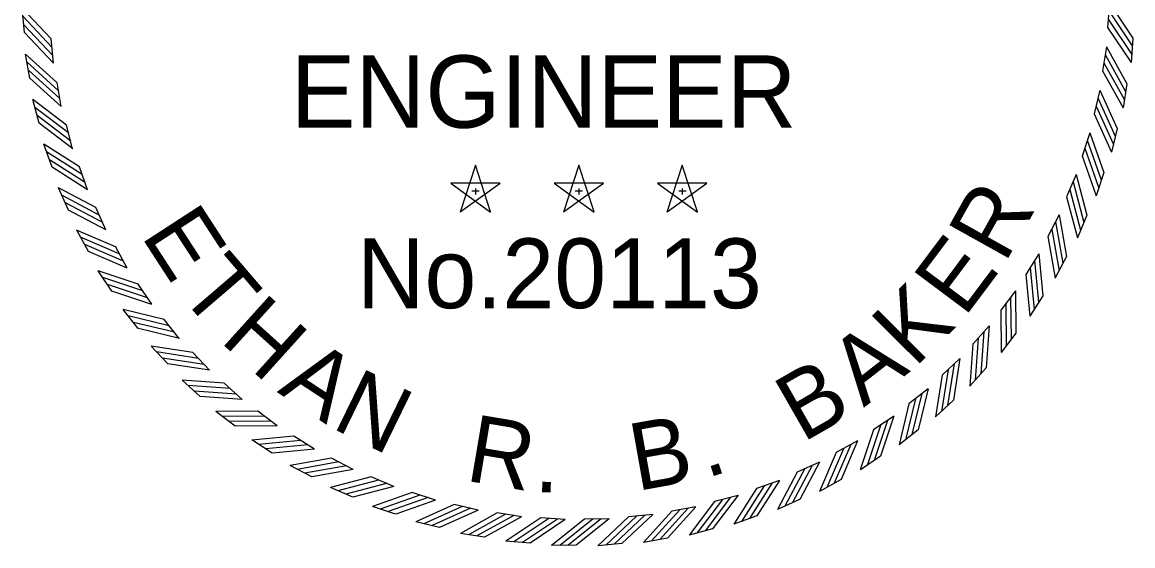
# Model space of a CAD drawing. Extents: x 18 to 14744716, y -5 to 1829144.
# Drawn here: x 42.058 to 44.119, y -4.046 to -3.074 of the extents above; entities that cross this region are included whole.
import ezdxf

# ---------------------------------------------------------------- set-up
doc = ezdxf.new("R2010")
doc.units = 0
doc.layers.add('B_StampERBB', color=7, linetype='Continuous')

msp = doc.modelspace()

# ---------------------------------------------------------------- linework, layer by layer
at = {"layer": 'B_StampERBB'}
for p, q in [((42.0623, -3.0928), (42.0581, -3.0478)), ((44.0753, -3.0382), (44.072, -3.0834)), ((42.1159, -3.1499), (42.1117, -3.1047)), ((44.1188, -3.1033), (44.1155, -3.1484)), ((44.0699, -3.1194), (44.0628, -3.1642)), ((42.0724, -3.1775), (42.0645, -3.1329)), ((42.1305, -3.2299), (42.1227, -3.1853)), ((44.1078, -3.1879), (44.1008, -3.2326)), ((44.0577, -3.1999), (44.047, -3.2439)), ((42.0895, -3.261), (42.078, -3.2173)), ((42.1517, -3.3085), (42.1402, -3.2646)), ((44.0899, -3.2712), (44.0792, -3.3152)), ((44.039, -3.2791), (44.0247, -3.3221)), ((42.1134, -3.3429), (42.0983, -3.3002)), ((42.1794, -3.385), (42.1642, -3.3423)), ((42.899, -3.3392), (42.8707, -3.4261)), ((42.9272, -3.426), (42.8991, -3.3391)), ((43.0909, -3.3392), (43.0626, -3.4261)), ((43.1191, -3.426), (43.091, -3.3391)), ((43.2828, -3.3392), (43.2545, -3.4261)), ((43.311, -3.426), (43.2828, -3.3391)), ((44.0138, -3.3564), (43.9959, -3.3981)), ((44.0652, -3.3528), (44.0509, -3.3958)), ((42.9446, -3.3724), (42.8533, -3.3723)), ((42.8534, -3.3724), (42.9272, -3.4261)), ((42.8708, -3.426), (42.9447, -3.3724)), ((43.1365, -3.3724), (43.0452, -3.3723)), ((43.0453, -3.3724), (43.1191, -3.4261)), ((43.0627, -3.426), (43.1366, -3.3724)), ((43.3284, -3.3724), (43.2371, -3.3723)), ((43.2372, -3.3724), (43.311, -3.4261)), ((43.2546, -3.426), (43.3285, -3.3724)), ((42.144, -3.4225), (42.1254, -3.3812)), ((42.8925, -3.387), (42.9061, -3.387)), ((42.8991, -3.3821), (42.8991, -3.3935)), ((43.0844, -3.387), (43.098, -3.387)), ((43.091, -3.3821), (43.091, -3.3935)), ((43.2763, -3.387), (43.2899, -3.387)), ((43.2829, -3.3821), (43.2829, -3.3935)), ((42.2132, -3.4591), (42.1946, -3.4177)), ((43.9822, -3.4315), (43.961, -3.4715)), ((44.0337, -3.4321), (44.016, -3.4737)), ((42.181, -3.4993), (42.1592, -3.4597)), ((42.2531, -3.53), (42.2311, -3.4903)), ((43.9446, -3.5036), (43.9202, -3.5418)), ((43.9959, -3.5086), (43.9747, -3.5485)), ((42.2243, -3.5728), (42.1992, -3.5351)), ((42.2986, -3.5974), (42.2735, -3.5597)), ((43.9012, -3.5725), (43.8737, -3.6085)), ((43.9519, -3.5816), (43.9275, -3.6197)), ((42.2735, -3.6424), (42.2454, -3.607)), ((42.3496, -3.6609), (42.3214, -3.6254)), ((43.8522, -3.6374), (43.8218, -3.6711)), ((43.902, -3.6507), (43.8745, -3.6867)), ((42.3283, -3.7078), (42.2974, -3.6748)), ((42.4057, -3.7199), (42.3746, -3.6868)), ((43.798, -3.6982), (43.7649, -3.7292)), ((43.8465, -3.7155), (43.8162, -3.7491)), ((42.3883, -3.7684), (42.3547, -3.7381)), ((42.4664, -3.7741), (42.4327, -3.7437)), ((43.739, -3.7542), (43.7035, -3.7824)), ((43.7859, -3.7755), (43.7529, -3.8065)), ((42.4531, -3.8238), (42.4171, -3.7964)), ((42.5314, -3.823), (42.4953, -3.7955)), ((43.6756, -3.8052), (43.6378, -3.8304)), ((43.7206, -3.8303), (43.6851, -3.8584)), ((42.5222, -3.8737), (42.4841, -3.8493)), ((42.6002, -3.8665), (42.562, -3.842)), ((43.6081, -3.8508), (43.5685, -3.8727)), ((42.6724, -3.9041), (42.6323, -3.8829)), ((43.5372, -3.8906), (43.4958, -3.9092)), ((43.6509, -3.8795), (43.6133, -3.9046)), ((42.5953, -3.9178), (42.5553, -3.8966)), ((42.7474, -3.9356), (42.7057, -3.9178)), ((43.4632, -3.9245), (43.4204, -3.9396)), ((43.5774, -3.9228), (43.5378, -3.9447)), ((42.6717, -3.9556), (42.6301, -3.9378)), ((42.8248, -3.9609), (42.7817, -3.9465)), ((43.3866, -3.9521), (43.3428, -3.9636)), ((42.751, -3.987), (42.7081, -3.9727)), ((42.904, -3.9796), (42.8599, -3.9689)), ((43.3081, -3.9733), (43.2634, -3.9812)), ((43.5006, -3.9598), (43.4594, -3.9784)), ((42.9844, -3.9917), (42.9396, -3.9847)), ((43.0656, -3.9972), (43.0204, -3.9939)), ((43.147, -3.9959), (43.1017, -3.9963)), ((43.228, -3.9879), (43.1828, -3.9921)), ((43.421, -3.9904), (43.3784, -4.0055)), ((42.8326, -4.0118), (42.7886, -4.0011)), ((43.3392, -4.0144), (43.2954, -4.0259)), ((42.916, -4.0297), (42.8713, -4.0227)), ((43.0005, -4.0407), (42.9554, -4.0374)), ((43.2556, -4.0314), (43.2111, -4.0393)), ((43.0857, -4.0446), (43.0405, -4.045)), ((43.1709, -4.0415), (43.1259, -4.0457))]:
    msp.add_line(p, q, dxfattribs=at)
for points in [[(42.1117, -3.1048), (42.0581, -3.0477)], [(44.0753, -3.0381), (44.1188, -3.1032)], [(42.1129, -3.1198), (42.0593, -3.0627)], [(44.0733, -3.0683), (44.1168, -3.1334)], [(44.0741, -3.0526), (44.1176, -3.1177)], [(42.1147, -3.1354), (42.0611, -3.0784)], [(44.072, -3.0834), (44.1155, -3.1485)], [(42.1159, -3.1499), (42.0623, -3.0929)], [(44.0698, -3.1193), (44.1078, -3.1878)], [(42.1226, -3.1853), (42.0645, -3.1329)], [(42.1251, -3.2002), (42.067, -3.1478)], [(44.0653, -3.1493), (44.1033, -3.2177)], [(44.0674, -3.1337), (44.1054, -3.2022)], [(42.1282, -3.2156), (42.0701, -3.1632)], [(44.0629, -3.1641), (44.1008, -3.2326)], [(42.1306, -3.23), (42.0725, -3.1775)], [(44.0541, -3.2139), (44.0863, -3.2853)], [(44.0577, -3.1998), (44.0899, -3.2712)], [(42.1402, -3.2647), (42.0779, -3.2172)], [(42.1439, -3.2793), (42.0816, -3.2319)], [(44.0507, -3.2293), (44.0829, -3.3006)], [(42.1482, -3.2944), (42.086, -3.247)], [(44.047, -3.2439), (44.0792, -3.3152)], [(42.1518, -3.3085), (42.0895, -3.2611)], [(44.0342, -3.2928), (44.0604, -3.3665)], [(44.039, -3.279), (44.0651, -3.3528)], [(42.1642, -3.3424), (42.0983, -3.3002)], [(42.1691, -3.3566), (42.1032, -3.3145)], [(44.0296, -3.3078), (44.0558, -3.3816)], [(42.1747, -3.3713), (42.1087, -3.3292)], [(44.0247, -3.322), (44.0509, -3.3958)], [(42.1794, -3.3851), (42.1135, -3.3429)], [(44.0137, -3.3564), (44.0337, -3.4321)], [(44.0079, -3.3697), (44.0279, -3.4454)], [(42.1946, -3.4178), (42.1254, -3.3812)], [(42.2007, -3.4316), (42.1314, -3.395)], [(43.996, -3.3981), (44.016, -3.4738)], [(44.002, -3.3843), (44.022, -3.46)], [(42.2074, -3.4457), (42.1382, -3.4092)], [(42.2133, -3.4591), (42.1441, -3.4225)], [(43.9822, -3.4314), (43.9959, -3.5085)], [(42.2311, -3.4904), (42.1591, -3.4597)], [(43.9683, -3.4583), (43.9819, -3.5353)], [(43.9753, -3.4442), (43.989, -3.5213)], [(42.2383, -3.5037), (42.1663, -3.4729)], [(43.9611, -3.4715), (43.9747, -3.5486)], [(42.2462, -3.5172), (42.1742, -3.4865)], [(42.2531, -3.53), (42.1811, -3.4993)], [(43.9367, -3.5158), (43.9439, -3.5937)], [(43.9446, -3.5036), (43.9519, -3.5815)], [(42.2735, -3.5598), (42.1992, -3.5351)], [(43.9202, -3.5418), (43.9275, -3.6197)], [(43.9285, -3.5292), (43.9357, -3.6071)], [(42.2817, -3.5724), (42.2074, -3.5477)], [(42.2907, -3.5853), (42.2164, -3.5606)], [(42.2987, -3.5975), (42.2244, -3.5728)], [(43.8922, -3.5839), (43.893, -3.6622)], [(43.9012, -3.5724), (43.902, -3.6507)], [(43.883, -3.5966), (43.8838, -3.6749)], [(42.3214, -3.6254), (42.2454, -3.607)], [(42.3307, -3.6373), (42.2546, -3.6189)], [(43.8737, -3.6085), (43.8745, -3.6867)], [(42.3407, -3.6494), (42.2647, -3.631)], [(42.3497, -3.6609), (42.2736, -3.6425)], [(43.8522, -3.6374), (43.8465, -3.7155)], [(43.8321, -3.66), (43.8264, -3.7381)], [(43.8423, -3.6481), (43.8367, -3.7262)], [(42.3746, -3.6869), (42.2973, -3.6748)], [(42.3849, -3.698), (42.3075, -3.6859)], [(43.8219, -3.6711), (43.8162, -3.7491)], [(42.3959, -3.7092), (42.3185, -3.6971)], [(42.4057, -3.7199), (42.3284, -3.7078)], [(43.7873, -3.708), (43.7752, -3.7853)], [(43.798, -3.6981), (43.7859, -3.7754)], [(43.765, -3.7292), (43.7529, -3.8065)], [(43.7761, -3.719), (43.764, -3.7963)], [(42.4328, -3.7437), (42.3547, -3.7381)], [(42.4438, -3.7539), (42.3658, -3.7483)], [(42.4557, -3.7642), (42.3777, -3.7585)], [(42.4664, -3.7741), (42.3884, -3.7684)], [(43.7275, -3.7631), (43.7091, -3.8392)], [(43.739, -3.7542), (43.7206, -3.8302)], [(43.7035, -3.7824), (43.6851, -3.8585)], [(43.7154, -3.7731), (43.697, -3.8492)], [(42.4954, -3.7956), (42.4171, -3.7964)], [(42.5073, -3.8048), (42.429, -3.8056)], [(43.6756, -3.8051), (43.6509, -3.8794)], [(42.52, -3.8141), (42.4417, -3.8149)], [(42.5314, -3.823), (42.4532, -3.8238)], [(43.6379, -3.8304), (43.6132, -3.9046)], [(43.6505, -3.8221), (43.6259, -3.8964)], [(43.6634, -3.8131), (43.6387, -3.8874)], [(42.562, -3.8421), (42.4841, -3.8494)], [(42.5746, -3.8503), (42.4967, -3.8576)], [(43.6082, -3.8507), (43.5775, -3.9227)], [(42.5881, -3.8585), (42.5101, -3.8658)], [(42.6003, -3.8665), (42.5223, -3.8737)], [(43.5685, -3.8727), (43.5378, -3.9447)], [(43.5818, -3.8656), (43.5511, -3.9376)], [(43.5954, -3.8576), (43.5647, -3.9296)], [(42.6323, -3.8829), (42.5552, -3.8966)], [(42.6456, -3.8901), (42.5685, -3.9038)], [(43.5372, -3.8906), (43.5007, -3.9598)], [(42.6596, -3.8972), (42.5825, -3.9108)], [(42.6724, -3.9041), (42.5954, -3.9178)], [(43.4959, -3.9092), (43.4593, -3.9784)], [(43.5097, -3.9032), (43.4731, -3.9724)], [(43.5239, -3.8964), (43.4873, -3.9656)], [(42.7057, -3.9178), (42.6301, -3.9378)], [(42.7195, -3.9239), (42.6439, -3.9439)], [(42.7341, -3.9298), (42.6584, -3.9498)], [(42.7475, -3.9356), (42.6718, -3.9556)], [(43.4347, -3.9347), (43.3926, -4.0007)], [(43.4494, -3.9291), (43.4073, -3.9951)], [(43.4632, -3.9244), (43.4211, -3.9904)], [(42.7818, -3.9466), (42.708, -3.9727)], [(42.796, -3.9515), (42.7223, -3.9776)], [(42.8111, -3.9561), (42.7373, -3.9823)], [(43.3726, -3.9556), (43.3251, -4.0179)], [(43.3867, -3.952), (43.3392, -4.0143)], [(43.4205, -3.9396), (43.3783, -4.0056)], [(42.8248, -3.9608), (42.7511, -3.987)], [(42.8599, -3.9689), (42.7886, -4.0011)], [(42.8746, -3.9726), (42.8032, -4.0048)], [(42.8899, -3.976), (42.8185, -4.0082)], [(43.2937, -3.9756), (43.2413, -4.0338)], [(43.3081, -3.9732), (43.2557, -4.0314)], [(43.3428, -3.9636), (43.2954, -4.0259)], [(43.3574, -3.9599), (43.31, -4.0222)], [(42.904, -3.9796), (42.8327, -4.0117)], [(42.9397, -3.9847), (42.8712, -4.0227)], [(42.9546, -3.9872), (42.8861, -4.0252)], [(42.9701, -3.9893), (42.9017, -4.0273)], [(42.9845, -3.9917), (42.916, -4.0297)], [(43.0205, -3.9939), (42.9554, -4.0374)], [(43.0355, -3.9951), (42.9704, -4.0386)], [(43.0512, -3.996), (42.9861, -4.0394)], [(43.0657, -3.9972), (43.0006, -4.0406)], [(43.1017, -3.9964), (43.0404, -4.0451)], [(43.1168, -3.9964), (43.0555, -4.0451)], [(43.1325, -3.9959), (43.0712, -4.0446)], [(43.1471, -3.9959), (43.0858, -4.0446)], [(43.1829, -3.9921), (43.1259, -4.0457)], [(43.1979, -3.9909), (43.1409, -4.0445)], [(43.2135, -3.9891), (43.1565, -4.0427)], [(43.228, -3.9879), (43.171, -4.0415)], [(43.2635, -3.9812), (43.211, -4.0393)], [(43.2783, -3.9787), (43.2259, -4.0368)]]:
    msp.add_lwpolyline(points, dxfattribs=at)

# ---------------------------------------------------------------- texts
for s, height, p in [('ENGINEER', 0.13433, (42.5566, -3.2696)), ('No.20113', 0.12953, (42.6794, -3.6046))]:
    msp.add_text(s, height=height, dxfattribs=at).set_placement(p)
for s, rotation, p in [('R', 60.8178, (43.8811, -3.5234)), ('E', 302.9873, (42.2772, -3.4696)), ('E', 53.157, (43.8061, -3.6236)), ('T', 310.6481, (42.3453, -3.5746)), ('K', 45.1314, (43.7139, -3.7168)), ('H', 317.9441, (42.4227, -3.6653)), ('A', 37.8354, (43.6195, -3.7897)), ('A', 326.6993, (42.5299, -3.76)), ('B', 29.8098, (43.5059, -3.8552)), ('N', 333.9953, (42.6293, -3.8258)), ('R', 350.4113, (42.878, -3.9244)), ('B', 10.1106, (43.198, -3.9443)), ('.', 18.1362, (43.327, -3.9209)), ('.', 358.4369, (43.0074, -3.9458))]:
    msp.add_text(s, height=0.125, rotation=rotation, dxfattribs=at).set_placement(p)

doc.saveas('drawing.dxf')
